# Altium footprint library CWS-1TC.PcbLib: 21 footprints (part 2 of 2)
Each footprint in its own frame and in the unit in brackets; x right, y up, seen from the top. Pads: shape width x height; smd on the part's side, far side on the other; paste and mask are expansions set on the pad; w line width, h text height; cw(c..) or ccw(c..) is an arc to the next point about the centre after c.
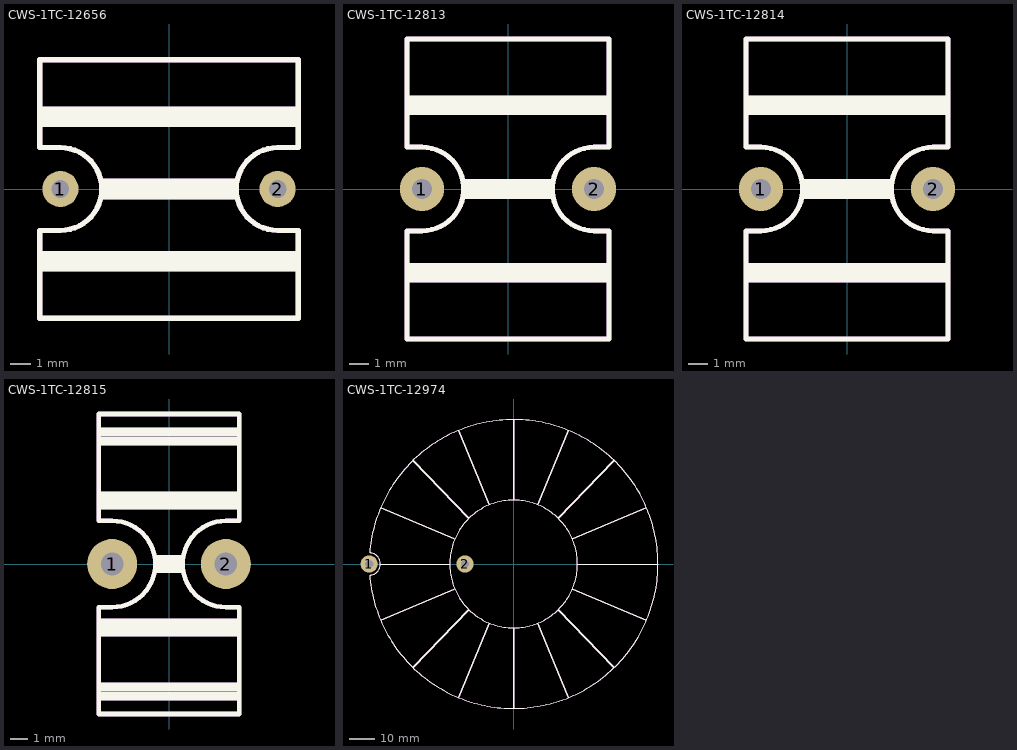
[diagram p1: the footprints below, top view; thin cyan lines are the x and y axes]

## CWS-1TC-12656 [mil]
pads (2):
  round 70 hole 34: 1(-210,0) 2(210,0)
Top Overlay:
  lines w10: -250,-250 250,-250 250,-80 210,-80 cw(c210,0) 210,80 250,80 250,250 -250,250 -250,80 -210,80 cw(c-210,0) -210,-80 -250,-80 -250,-250
  lines w19.68: -245,-150 245,-150 ; -245,-130 245,-130 ; -245,130 245,130 ; -245,150 245,150 ; -125,-10 125,-10 ; -125,10 125,10
Mechanical 29:
  lines w10: -250,-250 250,-250 250,-80 210,-80 cw(c210,0) 210,80 250,80 250,250 -250,250 -250,80 -210,80 cw(c-210,0) -210,-80 -250,-80 -250,-250
  lines w19.68: -245,-150 245,-150 ; -245,-130 245,-130 ; -245,130 245,130 ; -245,150 245,150 ; -125,-10 125,-10 ; -125,10 125,10
  text "'.Designator'" at -1750,-64.85 h400

## CWS-1TC-12813 [mil]
pads (2):
  round 90 hole 40: 1(-175,0) 2(175,0)
Top Overlay:
  lines w10: -205,-305 -205,-85 -175,-85 ccw(c-175,0) -175,85 -205,85 -205,305 205,305 205,85 175,85 ccw(c175,0) 175,-85 205,-85 205,-305 -205,-305
  lines w19.68: -200,-180 200,-180 ; -200,-160 200,-160 ; -200,160 200,160 ; -200,180 200,180 ; -85,-10 85,-10 ; -85,10 85,10
Mechanical 29:
  lines w10: -205,-305 -205,-85 -175,-85 ccw(c-175,0) -175,85 -205,85 -205,305 205,305 205,85 175,85 ccw(c175,0) 175,-85 205,-85 205,-305 -205,-305
  lines w19.68: -200,-180 200,-180 ; -200,-160 200,-160 ; -200,160 200,160 ; -200,180 200,180 ; -85,-10 85,-10 ; -85,10 85,10
  text "'.Designator'" at -1750,-64.85 h400

## CWS-1TC-12814 [mil]
pads (2):
  round 90 hole 40: 1(-175,0) 2(175,0)
Top Overlay:
  lines w10: -205,-305 205,-305 205,-85 175,-85 cw(c175,0) 175,85 205,85 205,305 -205,305 -205,85 -175,85 cw(c-175,0) -175,-85 -205,-85 -205,-305
  lines w19.68: -200,-180 200,-180 ; -200,-160 200,-160 ; -200,160 200,160 ; -200,180 200,180 ; -85,-10 85,-10 ; -85,10 85,10
Mechanical 29:
  lines w10: -205,-305 205,-305 205,-85 175,-85 cw(c175,0) 175,85 205,85 205,305 -205,305 -205,85 -175,85 cw(c-175,0) -175,-85 -205,-85 -205,-305
  lines w19.68: -200,-180 200,-180 ; -200,-160 200,-160 ; -200,160 200,160 ; -200,180 200,180 ; -85,-10 85,-10 ; -85,10 85,10
  text "'.Designator'" at -1750,-64.85 h400

## CWS-1TC-12815 [mil]
pads (2):
  round 110 hole 50: 1(-125,0) 2(125,0)
Top Overlay:
  lines w10: -155,-330 -155,-95 -125,-95 ccw(c-125,0) -125,95 -155,95 -155,330 155,330 155,95 125,95 ccw(c125,0) 125,-95 155,-95 155,-330 -155,-330
  lines w19.68: -150,-290 150,-290 ; -150,-270 150,-270 ; -150,-150 150,-150 ; -150,-130 150,-130 ; -150,130 150,130 ; -150,150 150,150 ; -150,270 150,270 ; -150,290 150,290 ; -25,-10 25,-10 ; -25,10 25,10
Mechanical 29:
  lines w10: -155,-330 -155,-95 -125,-95 ccw(c-125,0) -125,95 -155,95 -155,330 155,330 155,95 125,95 ccw(c125,0) 125,-95 155,-95 155,-330 -155,-330
  lines w19.68: -150,-290 150,-290 ; -150,-270 150,-270 ; -150,-150 150,-150 ; -150,-130 150,-130 ; -150,130 150,130 ; -150,150 150,150 ; -150,270 150,270 ; -150,290 150,290 ; -25,-10 25,-10 ; -25,10 25,10
  text "'.Designator'" at -1750,-64.85 h400

## CWS-1TC-12974 [mil]
pads (2):
  round 270 hole 130: 1(-2260,0) 2(-760,0)
Top Overlay:
  circle w10: c0,0 r1000
  lines w10: -2253.25,174.48 cw(c0,0) 2222.61,409.4 cw(c0,0) -2253.22,-174.87 ; -2253.22,174.87 cw(c-2260,0) -2253.06,-174.86 ; -2085,0 -1000,0 ; 1000,0 2260,0
  lines w19.68: -2076.66,-879.94 -925.72,-392.25 ; -2076.66,879.94 -925.72,392.25 ; -1569.86,-1615.14 -699.79,-717.66 ; -1569.86,1615.14 -699.79,717.66 ; -855.56,-2084.75 -381.53,-928.12 ; -855.56,2084.75 -381.53,928.12 ; 0,-2250 0,-1010 ; 0,1010 0,2250 ; 381.53,-928.12 855.56,-2084.75 ; 381.53,928.12 855.56,2084.75 ; 699.79,-717.66 1569.86,-1615.14 ; 699.79,717.66 1569.86,1615.14 ; 925.72,-392.25 2076.66,-879.94 ; 925.72,392.25 2076.66,879.94
Mechanical 29:
  circle w10: c0,0 r1000
  lines w10: -2253.25,174.48 cw(c0,0) 2222.61,409.4 cw(c0,0) -2253.22,-174.87 ; -2253.22,174.87 cw(c-2260,0) -2253.06,-174.86 ; -2085,0 -1000,0 ; 1000,0 2260,0
  lines w19.68: -2076.66,-879.94 -925.72,-392.25 ; -2076.66,879.94 -925.72,392.25 ; -1569.86,-1615.14 -699.79,-717.66 ; -1569.86,1615.14 -699.79,717.66 ; -855.56,-2084.75 -381.53,-928.12 ; -855.56,2084.75 -381.53,928.12 ; 0,-2250 0,-1010 ; 0,1010 0,2250 ; 381.53,-928.12 855.56,-2084.75 ; 381.53,928.12 855.56,2084.75 ; 699.79,-717.66 1569.86,-1615.14 ; 699.79,717.66 1569.86,1615.14 ; 925.72,-392.25 2076.66,-879.94 ; 925.72,392.25 2076.66,879.94
  text "'.Designator'" at -290,145.15 h400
